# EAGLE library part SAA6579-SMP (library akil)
RDS Demodulator
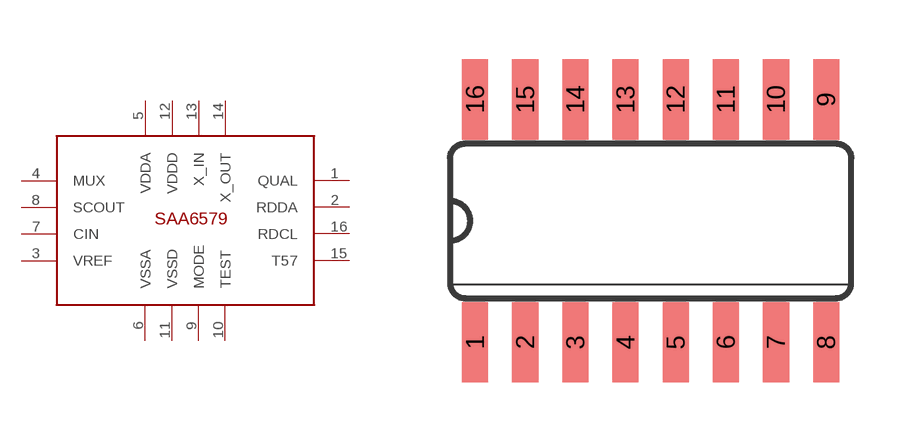
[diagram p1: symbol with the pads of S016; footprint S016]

Designator prefix -

## SAA6579-SMP  [S016]
1  QUAL
2  RDDA
3  VREF
4  MUX
5  VDDA
6  VSSA
7  CIN
8  SCOUT
9  MODE
10  TEST
11  VSSD
12  VDDD
13  X_IN
14  X_OUT
15  T57
16  RDCL

## Footprint S016 (pad centres in mm)
Small Outline Package 16 PIN
smd 0.66 x 2.032: 1 -0.635,-1.803; 2 0.635,-1.803; 3 1.905,-1.803; 4 3.175,-1.803; 5 4.445,-1.803; 6 5.715,-1.803; 7 6.985,-1.803; 8 8.255,-1.803; 9 8.255,4.343; 10 6.985,4.343; 11 5.715,4.343; 12 4.445,4.343; 13 3.175,4.343; 14 1.905,4.343; 15 0.635,4.343; 16 -0.635,4.343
